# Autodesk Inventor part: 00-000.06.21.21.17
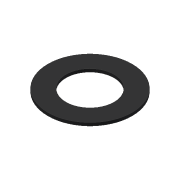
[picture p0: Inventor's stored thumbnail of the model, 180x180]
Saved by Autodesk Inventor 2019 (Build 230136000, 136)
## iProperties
Created: 2019-01
Part Number: 00-000.06.21.21.17
Material: Rubber
Document SubType Name: Modeling
Designer: m.vorobev
Density: 0.93 g/cm^3
Appearance: Rubber - Black
Author: m.vorobev
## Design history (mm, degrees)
sketch "Sketch1"
  geometry: L1 (8, 0.5)-(14, 0.5); L2 (14, 0.5)-(14, -0.5); L3 (14, -0.5)-(8, -0.5); L4 (8, -0.5)-(8, 0.5); L5 (0, 0)-(0, 5.055); 1 further point
  constraints: 10 end point, 2 parallel, 1 horizontal, 1 horizontal alignment, 1 midpoint, 1 perpendicular, 1 vertical
  dimensions: "d0" = 1 distance of L1.end L2.end; "d1" = 28 diameter of L2 L5; "d2" = 16 diameter of L4 L5
revolve "Revolution1" sketch "Sketch1" stored, may be unused: angle "d3" = 90 deg
body "Solid1"
